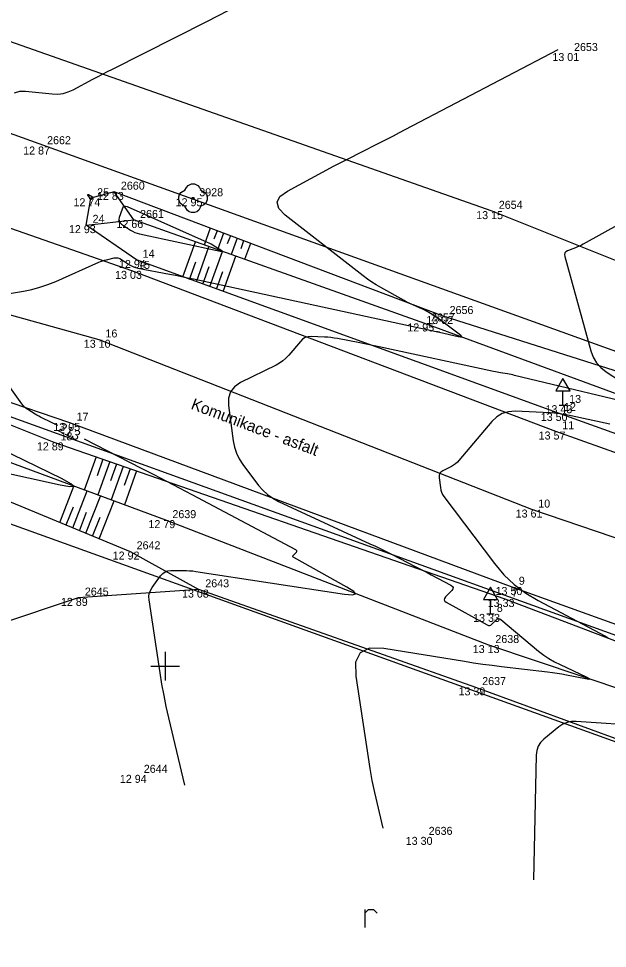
# Model space of a CAD drawing. Extents: x -703403 to -701924, y -1022520 to -1021856.
# Drawn here: x -702005.13 to -701984.54, y -1022334.87 to -1022302.35 of the extents above; entities that cross this region are included whole.
import ezdxf

# ---------------------------------------------------------------- set-up
doc = ezdxf.new("R2010")
doc.units = 0
for name, color, linetype in [('Ex_Contour Labels', 7, 'Continuous'), ('Ex_Major Contours', 7, 'Continuous'), ('Ex_Minor Contours', 7, 'Continuous'), ('Z_body', 7, 'Continuous'), ('Z_body_cisla', 7, 'Continuous'), ('Z_body_vysky_redukovane', 7, 'Continuous'), ('Z_dopravni_znacky', 7, 'Continuous'), ('Z_hektometricka_sit', 7, 'Continuous'), ('Z_hrany_paty', 7, 'Continuous'), ('Z_katastr_hranice', 7, 'Continuous'), ('Z_katastr_hranice_katastralni_uzemi', 7, 'Continuous'), ('Z_komunikace', 7, 'Continuous'), ('Z_komunikace_osa', 7, 'Continuous'), ('Z_pole_rozhranni', 7, 'Continuous'), ('Z_popisy', 7, 'Continuous'), ('Z_technicke_srafy', 7, 'Continuous'), ('Z_zelen_jednotliva', 7, 'Continuous'), ('Z_znaky_kultur', 7, 'Continuous')]:
    doc.layers.add(name, color=color, linetype=linetype)

# ---------------------------------------------------------------- blocks, each defined once
blk = doc.blocks.new('POINT_DISPLAY')
blk.add_line((0, 0), (0, 0))
blk = doc.blocks.new('Z24')
for p, q in [((-0.28, 0.28), (-0.23, 0.38)), ((-0.23, 0.38), (-0.17, 0.45)), ((-0.17, 0.45), (-0.05, 0.5)), ((-0.05, 0.5), (0.05, 0.5)), ((0.05, 0.5), (0.17, 0.45)), ((0.17, 0.45), (0.23, 0.38)), ((0.23, 0.38), (0.28, 0.28)), ((-0.5, 0.05), (-0.47, 0.13)), ((-0.5, -0.05), (-0.5, 0.05)), ((-0.47, 0.13), (-0.42, 0.2)), ((-0.42, 0.2), (-0.28, 0.28)), ((-0.03, -0.03), (-0.03, 0.03)), ((-0.03, 0.03), (0.03, 0.03)), ((0.03, 0.03), (0.03, -0.03)), ((0.28, 0.28), (0.42, 0.2)), ((0.42, 0.2), (0.47, 0.13)), ((0.47, 0.13), (0.5, 0.05)), ((0.5, 0.05), (0.5, -0.05)), ((-0.45, -0.17), (-0.5, -0.05)), ((-0.38, -0.23), (-0.45, -0.17)), ((-0.28, -0.28), (-0.38, -0.23)), ((-0.2, -0.42), (-0.28, -0.28)), ((0.03, -0.03), (-0.03, -0.03)), ((0.28, -0.28), (0.2, -0.42)), ((0.38, -0.23), (0.28, -0.28)), ((0.45, -0.17), (0.38, -0.23)), ((0.5, -0.05), (0.45, -0.17)), ((-0.13, -0.47), (-0.2, -0.42)), ((-0.05, -0.5), (-0.13, -0.47)), ((0.05, -0.5), (-0.05, -0.5)), ((0.13, -0.47), (0.05, -0.5)), ((0.2, -0.42), (0.13, -0.47))]:
    blk.add_line(p, q)
blk = doc.blocks.new('Z527')
for p, q in [((0, 0.93), (-0.25, 0.5)), ((0.25, 0.5), (0, 0.93)), ((-0.25, 0.5), (0.25, 0.5)), ((0, 0), (0, 0.5)), ((-0.13, 0), (0.13, 0))]:
    blk.add_line(p, q)
blk = doc.blocks.new('Z301')
for p, q in [((-0.13, 0.38), (-0.13, -0.25)), ((-0.13, 0.25), (0, 0.38)), ((0, 0.38), (0.17, 0.38)), ((0.17, 0.38), (0.3, 0.25))]:
    blk.add_line(p, q)

msp = doc.modelspace()

# ---------------------------------------------------------------- linework, layer by layer
at = {"layer": 'Ex_Major Contours'}
for points in [[(-702006.793, -1022312.183), (-702004.954, -1022311.877), (-702004.664, -1022311.82), (-702004.379, -1022311.744), (-702004.099, -1022311.65), (-702003.824, -1022311.538), (-702002.323, -1022310.869), (-702002.258, -1022310.842), (-702002.193, -1022310.818), (-702002.126, -1022310.798), (-702002.058, -1022310.781), (-702001.784, -1022310.72), (-702001.717, -1022310.712), (-702001.652, -1022310.717), (-702001.59, -1022310.736), (-702001.53, -1022310.768), (-702001.249, -1022310.955), (-702001.181, -1022310.996), (-702001.111, -1022311.029), (-702001.037, -1022311.055), (-702000.96, -1022311.073), (-701999.854, -1022311.283), (-701999.643, -1022311.324), (-701999.433, -1022311.366), (-701999.224, -1022311.409), (-701999.014, -1022311.454), (-701990.528, -1022313.29), (-701990.518, -1022313.292), (-701990.508, -1022313.294), (-701990.498, -1022313.296), (-701990.488, -1022313.298), (-701990.447, -1022313.305), (-701990.437, -1022313.306), (-701990.427, -1022313.308), (-701990.417, -1022313.31), (-701990.407, -1022313.313), (-701989.76, -1022313.469), (-701989.674, -1022313.483), (-701989.639, -1022313.475), (-701989.655, -1022313.442), (-701989.721, -1022313.385), (-701990.374, -1022312.898), (-701990.424, -1022312.862), (-701990.474, -1022312.826), (-701990.525, -1022312.792), (-701990.577, -1022312.759), (-701990.786, -1022312.629), (-701990.839, -1022312.597), (-701990.893, -1022312.567), (-701990.947, -1022312.539), (-701991.003, -1022312.513), (-701991.347, -1022312.361), (-701991.423, -1022312.326), (-701991.498, -1022312.29), (-701991.572, -1022312.252), (-701991.645, -1022312.212), (-701992.465, -1022311.753), (-701992.624, -1022311.66), (-701992.779, -1022311.561), (-701992.931, -1022311.456), (-701993.078, -1022311.346), (-701995.804, -1022309.219), (-701996.028, -1022308.988), (-701996.091, -1022308.771), (-701995.992, -1022308.567), (-701995.731, -1022308.378), (-701994.089, -1022307.502), (-701993.883, -1022307.393), (-701993.678, -1022307.285), (-701993.471, -1022307.178), (-701993.264, -1022307.073), (-701992.435, -1022306.653), (-701992.228, -1022306.548), (-701992.021, -1022306.442), (-701991.814, -1022306.335), (-701991.608, -1022306.227), (-701986.267, -1022303.43)], [(-702003.758, -1022316.579), (-702004.293, -1022316.322), (-702004.359, -1022316.289), (-702004.423, -1022316.255), (-702004.487, -1022316.218), (-702004.55, -1022316.18), (-702004.8, -1022316.023), (-702004.86, -1022315.982), (-702004.915, -1022315.935), (-702004.965, -1022315.883), (-702005.011, -1022315.826), (-702006.413, -1022313.876)], [(-701999.318, -1022329.162), (-701999.874, -1022326.808), (-701999.962, -1022326.414), (-702000.043, -1022326.02), (-702000.115, -1022325.624), (-702000.18, -1022325.226), (-702000.566, -1022322.683), (-702000.573, -1022322.565), (-702000.558, -1022322.453), (-702000.52, -1022322.346), (-702000.459, -1022322.245), (-702000.16, -1022321.833), (-702000.089, -1022321.755), (-702000.007, -1022321.699), (-701999.914, -1022321.665), (-701999.809, -1022321.654), (-701999.368, -1022321.651), (-701999.258, -1022321.652), (-701999.148, -1022321.658), (-701999.038, -1022321.669), (-701998.929, -1022321.683), (-701993.73, -1022322.478), (-701993.454, -1022322.505), (-701993.348, -1022322.472), (-701993.412, -1022322.382), (-701993.647, -1022322.233), (-701995.504, -1022321.2), (-701995.528, -1022321.182), (-701995.538, -1022321.162), (-701995.534, -1022321.139), (-701995.517, -1022321.115), (-701995.417, -1022321.014), (-701995.4, -1022320.99), (-701995.396, -1022320.968), (-701995.406, -1022320.948), (-701995.43, -1022320.93), (-701999.055, -1022319.009), (-701999.498, -1022318.775), (-701999.941, -1022318.542), (-702000.386, -1022318.311), (-702000.83, -1022318.081), (-702002.821, -1022317.054)]]:
    msp.add_lwpolyline(points, dxfattribs=at)
at = {"layer": 'Ex_Minor Contours'}
for points in [[(-702005.27, -1022304.939), (-702005.088, -1022304.884), (-702004.88, -1022304.881), (-702003.947, -1022304.977), (-702003.757, -1022304.984), (-702003.572, -1022304.962), (-702003.393, -1022304.912), (-702003.219, -1022304.835), (-702002.535, -1022304.47), (-702002.364, -1022304.379), (-702002.192, -1022304.29), (-702002.02, -1022304.201), (-702001.847, -1022304.113), (-701998.548, -1022302.442), (-701998.159, -1022302.244), (-701997.771, -1022302.045), (-701997.384, -1022301.845), (-701996.998, -1022301.644), (-701994.68, -1022300.43)], [(-701981.575, -1022308.13), (-701985.386, -1022310.233), (-701985.452, -1022310.268), (-701985.519, -1022310.301), (-701985.587, -1022310.331), (-701985.656, -1022310.36), (-701985.934, -1022310.469), (-701985.992, -1022310.501), (-701986.028, -1022310.545), (-701986.042, -1022310.601), (-701986.033, -1022310.667), (-701985.125, -1022313.967), (-701985.044, -1022314.188), (-701984.928, -1022314.383), (-701984.777, -1022314.553), (-701984.591, -1022314.697), (-701983.583, -1022315.351)], [(-701982.818, -1022316.024), (-701987.791, -1022314.826), (-701987.851, -1022314.813), (-701987.912, -1022314.8), (-701987.972, -1022314.788), (-701988.033, -1022314.777), (-701988.277, -1022314.737), (-701988.338, -1022314.727), (-701988.399, -1022314.716), (-701988.459, -1022314.704), (-701988.52, -1022314.691), (-701992.527, -1022313.824), (-701992.694, -1022313.788), (-701992.862, -1022313.754), (-701993.029, -1022313.72), (-701993.197, -1022313.688), (-701993.978, -1022313.539), (-701994.092, -1022313.52), (-701994.206, -1022313.505), (-701994.321, -1022313.494), (-701994.436, -1022313.487), (-701994.897, -1022313.469), (-701995.008, -1022313.476), (-701995.108, -1022313.506), (-701995.197, -1022313.56), (-701995.277, -1022313.636), (-701995.682, -1022314.118), (-701995.779, -1022314.222), (-701995.885, -1022314.314), (-701996, -1022314.395), (-701996.124, -1022314.465), (-701997.364, -1022315.08), (-701997.578, -1022315.222), (-701997.72, -1022315.403), (-701997.791, -1022315.622), (-701997.79, -1022315.879), (-701997.626, -1022317.116), (-701997.582, -1022317.339), (-701997.512, -1022317.55), (-701997.414, -1022317.75), (-701997.289, -1022317.939), (-701996.736, -1022318.674), (-701996.588, -1022318.847), (-701996.424, -1022318.998), (-701996.241, -1022319.127), (-701996.042, -1022319.234), (-701992.844, -1022320.715), (-701992.655, -1022320.804), (-701992.468, -1022320.894), (-701992.281, -1022320.986), (-701992.096, -1022321.081), (-701991.264, -1022321.51), (-701991.125, -1022321.582), (-701990.986, -1022321.654), (-701990.847, -1022321.727), (-701990.708, -1022321.801), (-701990.014, -1022322.168), (-701989.961, -1022322.207), (-701989.938, -1022322.251), (-701989.947, -1022322.299), (-701989.986, -1022322.352), (-701990.203, -1022322.573), (-701990.242, -1022322.626), (-701990.25, -1022322.675), (-701990.228, -1022322.72), (-701990.176, -1022322.759), (-701988.749, -1022323.553), (-701988.703, -1022323.571), (-701988.659, -1022323.573), (-701988.617, -1022323.559), (-701988.578, -1022323.528), (-701988.425, -1022323.372), (-701988.386, -1022323.342), (-701988.346, -1022323.331), (-701988.306, -1022323.338), (-701988.264, -1022323.364), (-701986.946, -1022324.471), (-701986.771, -1022324.608), (-701986.588, -1022324.733), (-701986.398, -1022324.846), (-701986.199, -1022324.946), (-701985.288, -1022325.368), (-701985.176, -1022325.425), (-701985.142, -1022325.457), (-701985.188, -1022325.463), (-701985.313, -1022325.443), (-701985.97, -1022325.312), (-701986.135, -1022325.281), (-701986.3, -1022325.253), (-701986.465, -1022325.229), (-701986.632, -1022325.208), (-701988.248, -1022325.019), (-701988.573, -1022324.979), (-701988.897, -1022324.936), (-701989.22, -1022324.889), (-701989.543, -1022324.839), (-701992.362, -1022324.382), (-701992.856, -1022324.373), (-701993.184, -1022324.531), (-701993.345, -1022324.858), (-701993.341, -1022325.352), (-701992.851, -1022328.581), (-701992.817, -1022328.792), (-701992.779, -1022329.002), (-701992.736, -1022329.212), (-701992.689, -1022329.42), (-701992.395, -1022330.669)], [(-701984.457, -1022316.537), (-701985.808, -1022316.245), (-701986.05, -1022316.198), (-701986.293, -1022316.161), (-701986.537, -1022316.135), (-701986.783, -1022316.12), (-701987.769, -1022316.081), (-701988.005, -1022316.096), (-701988.219, -1022316.161), (-701988.41, -1022316.275), (-701988.58, -1022316.439), (-701989.732, -1022317.806), (-701989.789, -1022317.868), (-701989.852, -1022317.923), (-701989.92, -1022317.971), (-701989.994, -1022318.012), (-701990.299, -1022318.163), (-701990.364, -1022318.207), (-701990.407, -1022318.262), (-701990.429, -1022318.329), (-701990.429, -1022318.408), (-701990.383, -1022318.753), (-701990.367, -1022318.837), (-701990.34, -1022318.916), (-701990.303, -1022318.992), (-701990.256, -1022319.063), (-701988.488, -1022321.41), (-701988.161, -1022321.798), (-701987.797, -1022322.144), (-701987.397, -1022322.447), (-701986.961, -1022322.707), (-701984.803, -1022323.839), (-701984.523, -1022323.996)], [(-702005.895, -1022318.17), (-702003.676, -1022318.657), (-702003.335, -1022318.717), (-702003.21, -1022318.704), (-702003.3, -1022318.615), (-702003.604, -1022318.451), (-702006.654, -1022316.965)], [(-701983.196, -1022327.1), (-701985.632, -1022326.931), (-701985.798, -1022326.934), (-701985.953, -1022326.967), (-701986.1, -1022327.03), (-701986.236, -1022327.123), (-701986.764, -1022327.555), (-701986.88, -1022327.671), (-701986.963, -1022327.802), (-701987.015, -1022327.949), (-701987.035, -1022328.112), (-701987.124, -1022332.475)]]:
    msp.add_lwpolyline(points, dxfattribs=at)
for points in [[(-702002.705, -1022308.508), (-702002.715, -1022308.509), (-702002.714, -1022308.519), (-702002.704, -1022308.538), (-702002.626, -1022308.654), (-702002.617, -1022308.664), (-702002.607, -1022308.668), (-702002.596, -1022308.667), (-702002.584, -1022308.661), (-702002.534, -1022308.624), (-702002.525, -1022308.615), (-702002.522, -1022308.607), (-702002.526, -1022308.599), (-702002.537, -1022308.592), (-702002.685, -1022308.516)], [(-702001.142, -1022309.787), (-702001.065, -1022309.825), (-702000.984, -1022309.855), (-702000.9, -1022309.877), (-701998.075, -1022310.485), (-701998.024, -1022310.493), (-701998.005, -1022310.489), (-701998.016, -1022310.472), (-701998.057, -1022310.443), (-701998.284, -1022310.301), (-701998.341, -1022310.266), (-701998.4, -1022310.234), (-701998.459, -1022310.204), (-701998.52, -1022310.176), (-702001.321, -1022308.933), (-702001.385, -1022308.915), (-702001.437, -1022308.923), (-702001.478, -1022308.956), (-702001.508, -1022309.016), (-702001.605, -1022309.305), (-702001.618, -1022309.374), (-702001.61, -1022309.435), (-702001.579, -1022309.489), (-702001.527, -1022309.535), (-702001.217, -1022309.743)]]:
    msp.add_lwpolyline(points, close=True, dxfattribs=at)
at = {"layer": 'Z_hektometricka_sit'}
for p, q in [((-702000, -1022324.5), (-702000, -1022325.5)), ((-702000.5, -1022325), (-701999.5, -1022325))]:
    msp.add_line(p, q, dxfattribs=at)
at = {"layer": 'Z_hrany_paty'}
for p, q in [((-702002.76, -1022309.57), (-702002.6, -1022308.63)), ((-702001.78, -1022308.41), (-702002.6, -1022308.63)), ((-701990.29, -1022312.75), (-702001.78, -1022308.41)), ((-702001.1, -1022309.39), (-702001.78, -1022308.41)), ((-702002.76, -1022309.57), (-702001.1, -1022309.39)), ((-702001.01, -1022310.79), (-702002.76, -1022309.57)), ((-701990.93, -1022313.01), (-702001.1, -1022309.39)), ((-701986.29, -1022316.14), (-702001.01, -1022310.79)), ((-701972.34, -1022318.46), (-701990.29, -1022312.75)), ((-701972.55, -1022319.77), (-701990.93, -1022313.01)), ((-702003.88, -1022317.17), (-702008.15, -1022315.47)), ((-701972.92, -1022320.95), (-701986.29, -1022316.14)), ((-701999.98, -1022319.89), (-702009.08, -1022316.52)), ((-701988.12, -1022322.65), (-702003.88, -1022317.17)), ((-702009.52, -1022317.55), (-702001.23, -1022320.99)), ((-701988.69, -1022324.26), (-701999.98, -1022319.89)), ((-702001.23, -1022320.99), (-701998.83, -1022322.32)), ((-701976, -1022327.29), (-701988.12, -1022322.65)), ((-701975.72, -1022328.63), (-701988.69, -1022324.26))]:
    msp.add_line(p, q, dxfattribs=at)
at = {"layer": 'Z_katastr_hranice'}
for p, q in [((-701974.6, -1022317.46), (-702046.47, -1022291.59)), ((-702012.68, -1022317.41), (-701952.94, -1022338.91))]:
    msp.add_line(p, q, dxfattribs=at)
at = {"layer": 'Z_katastr_hranice_katastralni_uzemi'}
msp.add_line((-701956.41, -1022333.98), (-702011.73, -1022314), dxfattribs=at)
msp.add_line((-701956.41, -1022333.98), (-702011.73, -1022314), dxfattribs=at)
at = {"layer": 'Z_komunikace'}
for p, q in [((-702001.17, -1022311.17), (-702007.66, -1022308.9)), ((-701986.34, -1022316.79), (-702001.17, -1022311.17)), ((-702003.33, -1022316.49), (-702009.39, -1022314.42)), ((-701987.87, -1022322.23), (-702003.33, -1022316.49)), ((-701973.3, -1022321.45), (-701986.34, -1022316.79)), ((-701975.68, -1022326.65), (-701987.87, -1022322.23))]:
    msp.add_line(p, q, dxfattribs=at)
at = {"layer": 'Z_komunikace_osa'}
for p, q in [((-702002.31, -1022313.58), (-702008.6, -1022311.84)), ((-701987.19, -1022319.52), (-702002.31, -1022313.58)), ((-701974.39, -1022323.86), (-701987.19, -1022319.52))]:
    msp.add_line(p, q, dxfattribs=at)
at = {"layer": 'Z_pole_rozhranni'}
for p, q in [((-701988.57, -1022309.08), (-702006.28, -1022302.85)), ((-701971.47, -1022315.94), (-701988.57, -1022309.08)), ((-701998.83, -1022322.32), (-702003.04, -1022322.61)), ((-701989.14, -1022325.74), (-701998.83, -1022322.32)), ((-702003.04, -1022322.61), (-702007.53, -1022324.11)), ((-701976.47, -1022330.41), (-701989.14, -1022325.74))]:
    msp.add_line(p, q, dxfattribs=at)
at = {"layer": 'Z_technicke_srafy'}
for p, q in [((-701998.43, -1022309.68), (-701998.64, -1022310.27)), ((-701998.19, -1022309.77), (-701998.3, -1022310.06)), ((-701997.96, -1022309.85), (-701998.17, -1022310.43)), ((-701997.72, -1022309.94), (-701997.83, -1022310.23)), ((-701999.38, -1022311.38), (-701998.94, -1022310.16)), ((-701997.49, -1022310.03), (-701997.7, -1022310.6)), ((-701997.26, -1022310.12), (-701997.36, -1022310.4)), ((-701997.02, -1022310.21), (-701997.23, -1022310.77)), ((-701998.91, -1022311.55), (-701998.47, -1022310.33)), ((-701998.44, -1022311.72), (-701998, -1022310.49)), ((-701999.15, -1022311.47), (-701998.93, -1022310.85)), ((-701997.97, -1022311.89), (-701997.53, -1022310.66)), ((-701998.68, -1022311.64), (-701998.46, -1022311.02)), ((-701998.21, -1022311.81), (-701997.99, -1022311.19)), ((-702002.41, -1022317.68), (-702002.83, -1022318.84)), ((-702002.18, -1022317.76), (-702002.38, -1022318.34)), ((-702001.94, -1022317.84), (-702002.36, -1022319.01)), ((-702001.7, -1022317.93), (-702001.91, -1022318.51)), ((-702001.47, -1022318.01), (-702001.89, -1022319.18)), ((-702001.23, -1022318.09), (-702001.44, -1022318.68)), ((-702001, -1022318.17), (-702001.42, -1022319.36)), ((-702003.69, -1022319.97), (-702003.19, -1022318.7)), ((-702003.23, -1022320.16), (-702002.73, -1022318.87)), ((-702002.77, -1022320.35), (-702002.26, -1022319.05)), ((-702002.31, -1022320.54), (-702001.79, -1022319.22)), ((-702003.46, -1022320.06), (-702003.21, -1022319.43)), ((-702003, -1022320.26), (-702002.75, -1022319.61)), ((-702002.54, -1022320.45), (-702002.28, -1022319.79))]:
    msp.add_line(p, q, dxfattribs=at)

# ---------------------------------------------------------------- block references
at = {"layer": 'Z_body'}
for p in [(-701985.93, -1022303.55), (-702004.36, -1022306.82), (-702002.6, -1022308.63), (-702001.78, -1022308.41), (-701999.03, -1022308.63), (-701988.57, -1022309.08), (-702002.76, -1022309.57), (-702001.1, -1022309.39), (-702001.01, -1022310.79), (-702001.17, -1022311.17), (-701990.29, -1022312.75), (-701990.93, -1022313.01), (-702002.31, -1022313.58), (-701986.29, -1022316.14), (-701986.1, -1022315.87), (-702003.33, -1022316.49), (-701986.34, -1022316.79), (-702003.88, -1022317.17), (-701987.19, -1022319.52), (-701999.98, -1022319.89), (-702001.23, -1022320.99), (-701998.83, -1022322.32), (-701987.87, -1022322.23), (-702003.04, -1022322.61), (-701988.12, -1022322.65), (-701988.63, -1022323.17), (-701988.69, -1022324.26), (-701989.14, -1022325.74), (-702000.98, -1022328.8), (-701991.01, -1022330.97)]:
    msp.add_blockref('POINT_DISPLAY', p, dxfattribs=at)
at = {"layer": 'Z_dopravni_znacky'}
for p in [(-701986.1, -1022315.87), (-701988.63, -1022323.17)]:
    msp.add_blockref('Z527', p, dxfattribs=at)
at = {"layer": 'Z_zelen_jednotliva'}
msp.add_blockref('Z24', (-701999.03, -1022308.63), dxfattribs=at)
at = {"layer": 'Z_znaky_kultur'}
msp.add_blockref('Z301', (-701992.89, -1022333.89), dxfattribs=at)

# ---------------------------------------------------------------- texts
at = {"layer": 'Ex_Contour Labels'}
msp.add_text('213', height=0.35, rotation=333.1443, dxfattribs=at).set_placement((-702003.772, -1022316.768))
at = {"layer": 'Z_body_cisla'}
for s, p in [('2653', (-701985.71, -1022303.48)), ('2662', (-702004.13, -1022306.74)), ('25', (-702002.38, -1022308.56)), ('2660', (-702001.55, -1022308.33)), ('3928', (-701998.81, -1022308.56)), ('2654', (-701988.34, -1022309)), ('24', (-702002.54, -1022309.49)), ('2661', (-702000.88, -1022309.32)), ('14', (-702000.79, -1022310.71)), ('15', (-702000.95, -1022311.1)), ('2656', (-701990.06, -1022312.68)), ('2657', (-701990.71, -1022312.94)), ('16', (-702002.09, -1022313.5)), ('12', (-701986.06, -1022316.07)), ('13', (-701985.88, -1022315.79)), ('17', (-702003.1, -1022316.41)), ('11', (-701986.12, -1022316.71)), ('18', (-702003.66, -1022317.1)), ('10', (-701986.96, -1022319.45)), ('2639', (-701999.75, -1022319.82)), ('2642', (-702001, -1022320.91)), ('2643', (-701998.6, -1022322.24)), ('9', (-701987.64, -1022322.15)), ('2645', (-702002.81, -1022322.53)), ('7', (-701987.89, -1022322.57)), ('8', (-701988.41, -1022323.1)), ('2638', (-701988.46, -1022324.19)), ('2637', (-701988.92, -1022325.66)), ('2644', (-702000.75, -1022328.73)), ('2636', (-701990.79, -1022330.9))]:
    msp.add_text(s, height=0.28, dxfattribs=at).set_placement(p)
at = {"layer": 'Z_body_vysky_redukovane'}
for s, p in [('13 01', (-701986.467, -1022303.83)), ('12 87', (-702004.967, -1022307.1)), ('12 74', (-702003.207, -1022308.91)), ('12 83', (-702002.387, -1022308.69)), ('12 95', (-701999.637, -1022308.91)), ('13 15', (-701989.13, -1022309.36)), ('12 93', (-702003.367, -1022309.85)), ('12 66', (-702001.707, -1022309.67)), ('12 94', (-702001.617, -1022311.07)), ('13 03', (-702001.753, -1022311.45)), ('13 02', (-701990.873, -1022313.03)), ('12 95', (-701991.537, -1022313.29)), ('13 10', (-702002.847, -1022313.86)), ('13 50', (-701986.873, -1022316.42)), ('13 43', (-701986.707, -1022316.15)), ('13 05', (-702003.913, -1022316.77)), ('13 57', (-701986.947, -1022317.07)), ('12 89', (-702004.487, -1022317.45)), ('13 61', (-701987.75, -1022319.8)), ('12 79', (-702000.587, -1022320.17)), ('12 92', (-702001.837, -1022321.27)), ('13 08', (-701999.413, -1022322.6)), ('13 50', (-701988.453, -1022322.51)), ('12 89', (-702003.647, -1022322.89)), ('13 33', (-701988.727, -1022322.93)), ('13 33', (-701989.237, -1022323.45)), ('13 13', (-701989.25, -1022324.54)), ('13 39', (-701989.747, -1022326.02)), ('12 94', (-702001.587, -1022329.08)), ('13 30', (-701991.593, -1022331.25))]:
    msp.add_text(s, height=0.28, dxfattribs=at).set_placement(p)
at = {"layer": 'Z_popisy'}
msp.add_text('Komunikace - asfalt', height=0.4, rotation=339.3, dxfattribs=at).set_placement((-701999.13, -1022315.99))

doc.saveas('drawing.dxf')
